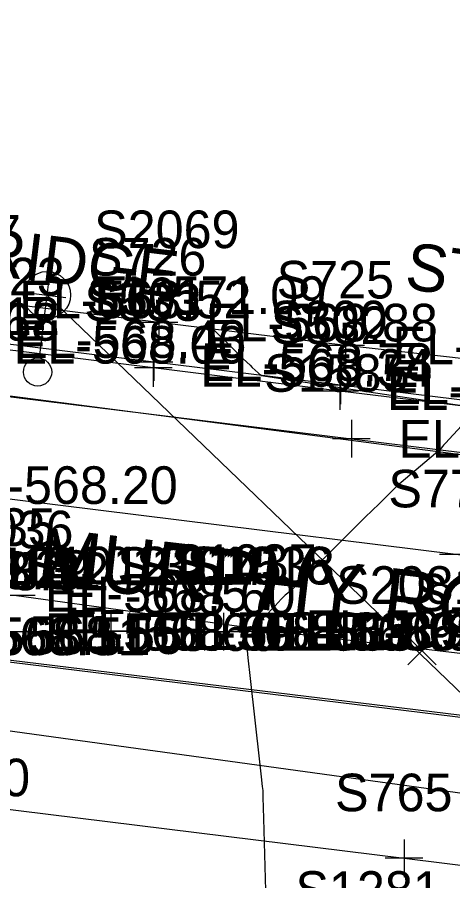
# Model space of a CAD drawing. Extents: x 1724534 to 1727318, y 657156 to 660047.
# Drawn here: x 1725691.4 to 1725737.7, y 658568.3 to 658660.1 of the extents above; entities that cross this region are included whole.
import ezdxf

# ---------------------------------------------------------------- set-up
doc = ezdxf.new("R2010")
doc.units = 0
for name, color, linetype in [('SURVEY - CENTERLINE - Preliminary', 7, 'Continuous'), ('SURVEY - CONTOURS - Intermediate with optional Text', 7, 'Continuous'), ('SURVEY - DRAINAGE - Area Shapes', 7, 'Continuous'), ('SURVEY - DRAINAGE - Storm Sewer', 7, 'Continuous'), ('SURVEY - DTM - Breaklines', 7, 'Continuous'), ('SURVEY - DTM - Breaklines - Points - Elevations', 7, 'Continuous'), ('SURVEY - DTM - Breaklines - Points - Locators', 7, 'Continuous'), ('SURVEY - DTM - Breaklines - Points - Numbers', 7, 'Continuous'), ('SURVEY - ROADSIDE BARRIERS - Points - Elevations', 7, 'Continuous'), ('SURVEY - ROADSIDE BARRIERS - Points - Locators', 7, 'Continuous'), ('SURVEY - ROADSIDE BARRIERS - Points - Numbers', 7, 'Continuous'), ('SURVEY - ROADSIDE BARRIERS with Text', 7, 'Continuous'), ('SURVEY - TRAFFIC CONTROL - Pavement Marking - Points - Elevations', 7, 'Continuous'), ('SURVEY - TRAFFIC CONTROL - Pavement Marking - Points - Locators', 7, 'Continuous'), ('SURVEY - TRAFFIC CONTROL - Pavement Marking - Points - Numbers', 7, 'Continuous'), ('SURVEY - TRAFFIC CONTROL - Pavement Marking with Text', 7, 'Continuous'), ('SURVEY - TRANSPORTATION - Features', 7, 'Continuous'), ('SURVEY - TRANSPORTATION - Features - Points - Elevations', 7, 'Continuous'), ('SURVEY - TRANSPORTATION - Features - Points - Locators', 7, 'Continuous'), ('SURVEY - TRANSPORTATION - Features - Points - Numbers', 7, 'Continuous'), ('SURVEY - TRANSPORTATION - Roads', 7, 'Continuous'), ('SURVEY - TRANSPORTATION - Roads - Points - Elevations', 7, 'Continuous'), ('SURVEY - TRANSPORTATION - Roads - Points - Locators', 7, 'Continuous'), ('SURVEY - TRANSPORTATION - Roads - Points - Numbers', 7, 'Continuous'), ('SURVEY - TRANSPORTATION - Roads Text', 7, 'Continuous'), ('SURVEY - UTILITIES - Electric (Lighting) - Points - Elevations', 7, 'Continuous'), ('SURVEY - UTILITIES - Electric (Lighting) - Points - Locators', 7, 'Continuous'), ('SURVEY - UTILITIES - Electric (Lighting) - Points - Numbers', 7, 'Continuous'), ('SURVEY - UTILITIES - Electric (Lighting) with Text', 7, 'Continuous'), ('SURVEY - UTILITIES - Low Wire Crossings', 7, 'Continuous'), ('SURVEY - UTILITIES - Low Wire Crossings - Points - Numbers', 7, 'Continuous'), ('SURVEY - UTILITIES - Overhead Wire Crossings', 7, 'Continuous'), ('SURVEY - UTILITIES - Poles and Miscellaneous with Text', 7, 'Continuous'), ('SURVEY - UTILITIES - Water with Text', 7, 'Continuous')]:
    doc.layers.add(name, color=color, linetype=linetype)

msp = doc.modelspace()

# ---------------------------------------------------------------- linework, layer by layer
at = {"layer": 'SURVEY - CENTERLINE - Preliminary'}
msp.add_line((1725165.112, 658655.739), (1725772.853, 658581.708), dxfattribs=at)
msp.add_line((1725165.112, 658655.739), (1725772.853, 658581.708), dxfattribs=at)
at = {"layer": 'SURVEY - CONTOURS - Intermediate with optional Text'}
msp.add_lwpolyline([(1725712.196, 658626.918), (1725714.838, 658624.329), (1725715.359, 658623.821), (1725715.788, 658623.405), (1725716.126, 658623.083), (1725716.373, 658622.855), (1725717.313, 658622.004), (1725721.475, 658621.372), (1725721.993, 658621.294), (1725725.734, 658620.726), (1725725.91, 658620.7), (1725726.13, 658620.667), (1725734.734, 658619.391), (1725735.5, 658619.278), (1725740.396, 658618.551), (1725737.328, 658615.239), (1725736.961, 658614.841), (1725736.716, 658614.573), (1725736.594, 658614.437), (1725736.312, 658614.11), (1725732.206, 658610.623), (1725731.76, 658610.215), (1725730.976, 658609.462), (1725729.854, 658608.363), (1725728.393, 658606.918), (1725724.046, 658602.605), (1725722.599, 658601.173), (1725721.52, 658600.111), (1725720.807, 658599.42), (1725720.461, 658599.1), (1725719.881, 658598.616), (1725719.766, 658598.517), (1725719.682, 658598.441), (1725719.63, 658598.388), (1725719.459, 658598.202), (1725718.805, 658597.515), (1725717.643, 658596.299), (1725717.283, 658595.929), (1725717.214, 658595.861), (1725717.125, 658595.786), (1725717.079, 658595.746), (1725716.4, 658595.193), (1725716.266, 658595.089), (1725716.147, 658595.006), (1725716.043, 658594.944), (1725715.954, 658594.903), (1725715.737, 658594.823), (1725715.702, 658594.484), (1725715.757, 658593.528), (1725715.904, 658591.955), (1725716.142, 658589.765), (1725717.147, 658580.902), (1725717.327, 658579.294), (1725717.437, 658578.28), (1725717.478, 658577.86), (1725717.495, 658577.531), (1725717.507, 658577.153), (1725717.572, 658574.872), (1725717.779, 658567.216)], dxfattribs=at)
at = {"layer": 'SURVEY - DRAINAGE - Area Shapes'}
msp.add_lwpolyline([(1725876.527, 658537.521), (1725880.453, 658568.253), (1725462.782, 658619.36), (1725459.014, 658588.567)], close=True, dxfattribs=at)
at = {"layer": 'SURVEY - DRAINAGE - Storm Sewer'}
msp.add_lwpolyline([(1725899.594, 658555.371), (1725464.565, 658615.304), (1725129.381, 658652.795)], dxfattribs=at)
at = {"layer": 'SURVEY - DTM - Breaklines'}
msp.add_lwpolyline([(1725923.442, 658596.261), (1725920.349, 658596.664), (1725900.537, 658599.315), (1725880.703, 658601.788), (1725860.867, 658604.256), (1725841.017, 658606.73), (1725821.164, 658609.108), (1725805.637, 658611.084), (1725785.8, 658613.524), (1725762.697, 658616.458), (1725748.853, 658618.143), (1725745.613, 658618.535), (1725725.762, 658620.955), (1725705.909, 658623.419), (1725686.061, 658625.875)], dxfattribs=at)
at = {"layer": 'SURVEY - DTM - Breaklines - Points - Locators'}
for p, q in [((1725705.909, 658625.419), (1725705.909, 658621.419)), ((1725707.909, 658623.419), (1725703.909, 658623.419)), ((1725725.762, 658622.955), (1725725.762, 658618.955)), ((1725727.762, 658620.955), (1725723.762, 658620.955))]:
    msp.add_line(p, q, dxfattribs=at)
at = {"layer": 'SURVEY - ROADSIDE BARRIERS - Points - Locators'}
for p, q in [((1725706.432, 658629.625), (1725706.432, 658625.625)), ((1725708.432, 658627.625), (1725704.432, 658627.625)), ((1725726.297, 658627.19), (1725726.297, 658623.19)), ((1725728.297, 658625.19), (1725724.297, 658625.19))]:
    msp.add_line(p, q, dxfattribs=at)
at = {"layer": 'SURVEY - ROADSIDE BARRIERS with Text'}
msp.add_lwpolyline([(1725749.441, 658623.208), (1725747.683, 658622.944), (1725746.171, 658622.954), (1725726.297, 658625.19), (1725706.432, 658627.625), (1725686.585, 658630.082), (1725666.736, 658632.525), (1725646.891, 658635.007), (1725627.042, 658637.458), (1725607.192, 658639.897), (1725587.342, 658642.328), (1725567.496, 658644.799), (1725547.649, 658647.261), (1725530.293, 658649.414), (1725527.821, 658649.879), (1725526.283, 658650.157), (1725524.746, 658650.804)], dxfattribs=at)
at = {"layer": 'SURVEY - TRAFFIC CONTROL - Pavement Marking - Points - Locators'}
for p, q in [((1725740.298, 658602.97), (1725736.298, 658602.97)), ((1725693.276, 658598.614), (1725689.276, 658598.614)), ((1725717.028, 658597.036), (1725717.028, 658593.036)), ((1725701.302, 658596.79), (1725701.302, 658592.79)), ((1725703.302, 658596.783), (1725703.302, 658592.783)), ((1725711.301, 658596.73), (1725711.301, 658592.73)), ((1725713.302, 658596.741), (1725713.302, 658592.741)), ((1725718.783, 658596.792), (1725718.783, 658592.792)), ((1725719.009, 658596.766), (1725719.009, 658592.766)), ((1725693.302, 658594.733), (1725689.302, 658594.733)), ((1725703.302, 658594.79), (1725699.302, 658594.79)), ((1725705.302, 658594.783), (1725701.302, 658594.783)), ((1725713.301, 658594.73), (1725709.301, 658594.73)), ((1725715.302, 658594.741), (1725711.302, 658594.741)), ((1725719.028, 658595.036), (1725715.028, 658595.036)), ((1725720.783, 658594.792), (1725716.783, 658594.792)), ((1725721.009, 658594.766), (1725717.009, 658594.766)), ((1725732.511, 658572.646), (1725732.511, 658568.646)), ((1725734.511, 658570.646), (1725730.511, 658570.646))]:
    msp.add_line(p, q, dxfattribs=at)
at = {"layer": 'SURVEY - TRAFFIC CONTROL - Pavement Marking with Text'}
for points in [[(1725469.93, 658636.195), (1725476.311, 658635.371), (1725478.295, 658635.122), (1725516.011, 658630.481), (1725599.369, 658620.164), (1725678.757, 658610.338), (1725738.298, 658602.97), (1725780.716, 658597.719), (1725790.639, 658596.491), (1725852.127, 658588.674), (1725871.961, 658586.151), (1725916.153, 658580.463)], [(1725507.893, 658598.435), (1725611.44, 658585.624), (1725663.045, 658579.239), (1725732.511, 658570.646), (1725771.433, 658565.831), (1725828.993, 658558.789), (1725876.604, 658552.91), (1725911.384, 658548.615)], [(1725691.276, 658598.614), (1725717.028, 658595.036), (1725719.009, 658594.766), (1725742.941, 658591.917), (1725766.76, 658588.985), (1725807.969, 658583.629), (1725837.716, 658579.798), (1725859.541, 658577.092), (1725887.31, 658573.624), (1725917.054, 658569.88)], [(1725691.302, 658594.733), (1725701.302, 658594.79), (1725703.302, 658594.783), (1725711.301, 658594.73), (1725713.302, 658594.741), (1725718.783, 658594.792)]]:
    msp.add_lwpolyline(points, dxfattribs=at)
at = {"layer": 'SURVEY - TRANSPORTATION - Features'}
msp.add_lwpolyline([(1725923.364, 658595.652), (1725920.271, 658596.054), (1725900.459, 658598.705), (1725880.625, 658601.178), (1725860.79, 658603.646), (1725840.941, 658606.12), (1725821.088, 658608.498), (1725805.562, 658610.474), (1725785.723, 658612.914), (1725762.62, 658615.849), (1725748.776, 658617.533), (1725745.535, 658617.925), (1725725.684, 658620.345), (1725705.833, 658622.809), (1725685.985, 658625.265)], dxfattribs=at)
at = {"layer": 'SURVEY - TRANSPORTATION - Features - Points - Locators'}
for p, q in [((1725705.833, 658624.809), (1725705.833, 658620.809)), ((1725707.833, 658622.809), (1725703.833, 658622.809)), ((1725725.684, 658622.345), (1725725.684, 658618.345)), ((1725727.684, 658620.345), (1725723.684, 658620.345))]:
    msp.add_line(p, q, dxfattribs=at)
at = {"layer": 'SURVEY - TRANSPORTATION - Roads'}
msp.add_lwpolyline([(1725603.861, 658630.44), (1725726.921, 658615.268), (1725763.101, 658610.806), (1725790.88, 658607.344), (1725824.612, 658603.138), (1725872.227, 658597.261), (1725926.076, 658590.615)], dxfattribs=at)
at = {"layer": 'SURVEY - TRANSPORTATION - Roads - Points - Locators'}
for p, q in [((1725726.921, 658617.268), (1725726.921, 658613.268)), ((1725728.921, 658615.268), (1725724.921, 658615.268))]:
    msp.add_line(p, q, dxfattribs=at)
at = {"layer": 'SURVEY - UTILITIES - Electric (Lighting) - Points - Locators'}
for p, q in [((1725694.3, 658628.563), (1725694.786, 658632.533)), ((1725692.558, 658630.791), (1725696.528, 658630.305))]:
    msp.add_line(p, q, dxfattribs=at)
at = {"layer": 'SURVEY - UTILITIES - Electric (Lighting) with Text'}
msp.add_line((1725693.712, 658623.859), (1725694.228, 658628.078), dxfattribs=at)
for centre, radius in [((1725694.532, 658630.56), 2.5), ((1725693.53, 658622.371), 1.5)]:
    msp.add_circle(centre, radius, dxfattribs=at)
at = {"layer": 'SURVEY - UTILITIES - Low Wire Crossings'}
for p, q in [((1725732.923, 658594.21), (1725735.923, 658591.21)), ((1725735.923, 658594.21), (1725732.923, 658591.21)), ((1725734.423, 658592.71), (1725734.423, 658592.71))]:
    msp.add_line(p, q, dxfattribs=at)
at = {"layer": 'SURVEY - UTILITIES - Overhead Wire Crossings'}
msp.add_line((1725694.543, 658630.548), (1725787.864, 658540.793), dxfattribs=at)
at = {"layer": 'SURVEY - UTILITIES - Water with Text'}
msp.add_lwpolyline([(1725847.724, 658579.712), (1725846.548, 658599.52), (1725380.522, 658660.104)], dxfattribs=at)

# ---------------------------------------------------------------- texts
at = {"layer": 'SURVEY - DTM - Breaklines - Points - Elevations'}
for s, p in [('EL-568.12', (1725671.211, 658626.311)), ('EL-568.43', (1725691.061, 658623.875)), ('EL-568.78', (1725710.909, 658621.419)), ('EL-569.16', (1725730.762, 658618.955))]:
    msp.add_text(s, height=4, dxfattribs=at).set_placement(p)
at = {"layer": 'SURVEY - DTM - Breaklines - Points - Numbers'}
for s, p in [('S301', (1725698.731, 658628.419)), ('S300', (1725718.253, 658625.955))]:
    msp.add_text(s, height=4, dxfattribs=at).set_placement(p)
at = {"layer": 'SURVEY - ROADSIDE BARRIERS - Points - Elevations'}
for s, p in [('EL-568.23', (1725671.736, 658630.525)), ('EL-568.52', (1725691.585, 658628.082)), ('EL-568.88', (1725711.432, 658625.625)), ('EL-569.30', (1725731.297, 658623.19))]:
    msp.add_text(s, height=4, dxfattribs=at).set_placement(p)
at = {"layer": 'SURVEY - ROADSIDE BARRIERS - Points - Numbers'}
for s, p in [('S727', (1725679.249, 658635.082)), ('S726', (1725698.986, 658632.625)), ('S725', (1725718.961, 658630.19))]:
    msp.add_text(s, height=4, dxfattribs=at).set_placement(p)
at = {"layer": 'SURVEY - ROADSIDE BARRIERS with Text'}
msp.add_text('JERSEY BARRIER WALL/BRIDGE', height=5, rotation=352.99509, dxfattribs=at).set_placement((1725603.82, 658643.041))
at = {"layer": 'SURVEY - TRAFFIC CONTROL - Pavement Marking - Points - Elevations'}
for s, p in [('EL-568.20', (1725683.757, 658608.338)), ('EL-568.29', (1725674.455, 658599.405)), ('EL-568.31', (1725675.578, 658599.268)), ('EL-568.32', (1725676.44, 658599.158)), ('EL-568.57', (1725694.294, 658596.874)), ('EL-568.60', (1725696.276, 658596.614)), ('EL-569.01', (1725722.028, 658593.036)), ('EL-568.51', (1725680.31, 658592.248)), ('EL-568.51', (1725680.86, 658592.264)), ('EL-568.55', (1725684.309, 658592.376)), ('EL-568.66', (1725694.303, 658592.7)), ('EL-568.69', (1725696.302, 658592.733)), ('EL-568.81', (1725706.302, 658592.79)), ('EL-568.83', (1725708.302, 658592.783)), ('EL-568.95', (1725716.301, 658592.73)), ('EL-568.97', (1725718.302, 658592.741)), ('EL-569.05', (1725723.783, 658592.792)), ('EL-569.05', (1725724.009, 658592.766)), ('EL-568.30', (1725668.045, 658577.239))]:
    msp.add_text(s, height=4, dxfattribs=at).set_placement(p)
at = {"layer": 'SURVEY - TRAFFIC CONTROL - Pavement Marking - Points - Numbers'}
for s, p in [('S776', (1725730.852, 658607.97)), ('S1035', (1725680.006, 658603.874)), ('S1036', (1725681.878, 658603.614)), ('S1010', (1725679.842, 658599.7)), ('S1011', (1725682.172, 658599.733)), ('S1012', (1725692.014, 658599.79)), ('S1013', (1725694.014, 658599.783)), ('S1014', (1725702.013, 658599.73)), ('S1015', (1725704.014, 658599.741)), ('S1037', (1725707.74, 658600.036)), ('S1016', (1725709.385, 658599.792)), ('S1038', (1725709.674, 658599.766)), ('S1039', (1725733.638, 658596.917)), ('S765', (1725725.175, 658575.646))]:
    msp.add_text(s, height=4, dxfattribs=at).set_placement(p)
at = {"layer": 'SURVEY - TRANSPORTATION - Features - Points - Elevations'}
for s, p in [('EL-567.68', (1725671.135, 658625.701)), ('EL-568.00', (1725690.985, 658623.265)), ('EL-568.34', (1725710.833, 658620.809)), ('EL-568.73', (1725730.684, 658618.345))]:
    msp.add_text(s, height=4, dxfattribs=at).set_placement(p)
at = {"layer": 'SURVEY - TRANSPORTATION - Features - Points - Numbers'}
for s, p in [('S533', (1725698.497, 658627.809)), ('S532', (1725718.348, 658625.345))]:
    msp.add_text(s, height=4, dxfattribs=at).set_placement(p)
at = {"layer": 'SURVEY - TRANSPORTATION - Roads - Points - Elevations'}
msp.add_text('EL-568.82', height=4, dxfattribs=at).set_placement((1725731.921, 658613.268))
at = {"layer": 'SURVEY - TRANSPORTATION - Roads - Points - Numbers'}
for s, p in [('S1585', (1725717.633, 658620.268)), ('S1281', (1725720.962, 658565.27))]:
    msp.add_text(s, height=4, dxfattribs=at).set_placement(p)
at = {"layer": 'SURVEY - TRANSPORTATION - Roads Text'}
msp.add_text('MURPHY ROAD (ASP.)', height=6, rotation=353.37384, dxfattribs=at).set_placement((1725693.293, 658599.901))
at = {"layer": 'SURVEY - UTILITIES - Electric (Lighting) - Points - Elevations'}
msp.add_text('EL-571.09', height=4, dxfattribs=at).set_placement((1725699.543, 658628.548))
at = {"layer": 'SURVEY - UTILITIES - Electric (Lighting) - Points - Numbers'}
msp.add_text('S2069', height=4, dxfattribs=at).set_placement((1725699.543, 658635.548))
at = {"layer": 'SURVEY - UTILITIES - Low Wire Crossings - Points - Numbers'}
msp.add_text('S2081', height=4, dxfattribs=at).set_placement((1725725.293, 658597.71))
at = {"layer": 'SURVEY - UTILITIES - Poles and Miscellaneous with Text'}
msp.add_text('STREET LIGHTING', height=5, rotation=352.4426, dxfattribs=at).set_placement((1725732.466, 658631.241))

doc.saveas('drawing.dxf')
